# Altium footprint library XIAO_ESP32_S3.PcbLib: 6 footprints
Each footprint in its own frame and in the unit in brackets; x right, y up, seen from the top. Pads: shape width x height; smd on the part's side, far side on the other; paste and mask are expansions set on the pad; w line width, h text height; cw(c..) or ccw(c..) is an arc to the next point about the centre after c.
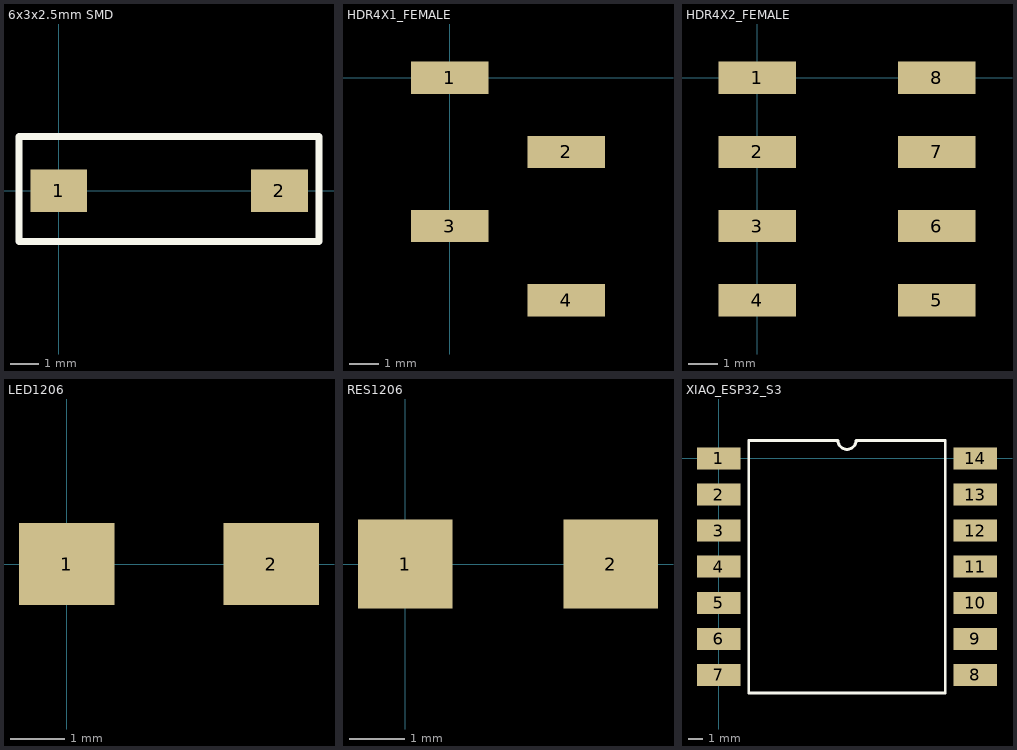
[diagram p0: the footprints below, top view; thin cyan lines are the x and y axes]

## 6x3x2.5mm SMD [mm]
pads (2):
  rect 2x1.5 smd: 1(0,0) 2(7.75,0)
Top Overlay:
  lines w0.254: -1.397,-1.778 8.89,-1.778 9.144,-1.778 9.144,1.905 -1.397,1.905 -1.397,-1.778
3D body "6x3mm Button.stp": height 2.54, standoff -0.03, extent -0.076,-1.791 7.696,1.791

## HDR4X1_FEMALE [mm]
pads (4):
  rect 2.65x1.1 smd: 1(0,0) 2(4,-2.54) 3(0,-5.08) 4(4,-7.62)
3D body "2MM-SMD-PIN-HEADER-FEMALE.STEP": height 2.33, standoff 0.01, extent -0.762,-7.703 4.738,0.337

## HDR4X2_FEMALE [mm]
pads (8):
  rect 2.65x1.1 smd: 1(0,0) 2(0,-2.54) 3(0,-5.08) 4(0,-7.62) 5(6.15,-7.62) 6(6.15,-5.08) 7(6.15,-2.54) 8(6.15,0)
3D body "Harwin-M20-Double-Row-SMT-8P_.STEP": height 7.5, standoff -0.03, extent -0.369,-8.89 6.211,1.27

## LED1206 [mm]
pads (2):
  rect 1.75x1.5 smd: 1(0,0) 2(3.75,0)
3D body "SMD LED -1206.step": height 1.1, standoff 0, extent 0.28,-0.813 3.48,0.787

## RES1206 [mm]
pads (2):
  rect 1.7x1.6 smd: 1(0,0) 2(3.7,0)
3D body "RC1206.stp": height 0.55, standoff 0, extent 0.253,-0.787 3.353,0.813

## XIAO_ESP32_S3 [mm]
pads (14):
  rect 3x1.52 smd: 1(0,0) 2(0,-2.5) 3(0,-5) 4(0,-7.5) 5(0,-10) 6(0,-12.5) 7(0,-15) 8(17.78,-15) 9(17.78,-12.5) 10(17.78,-10) 11(17.78,-7.5) 12(17.78,-5) 13(17.78,-2.5) 14(17.78,0)
Top Overlay:
  lines w0.2: 2.085,-16.25 15.695,-16.25 15.695,1.25 9.515,1.25 cw(c8.89,1.25) 8.265,1.25 2.085,1.25 2.085,-16.25
3D body "Seeed Studio XIAO-ESP32-S3-Sense_ALONE.STEP": height 4.47, standoff 0.01, extent -0.015,-17.995 17.765,4.487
